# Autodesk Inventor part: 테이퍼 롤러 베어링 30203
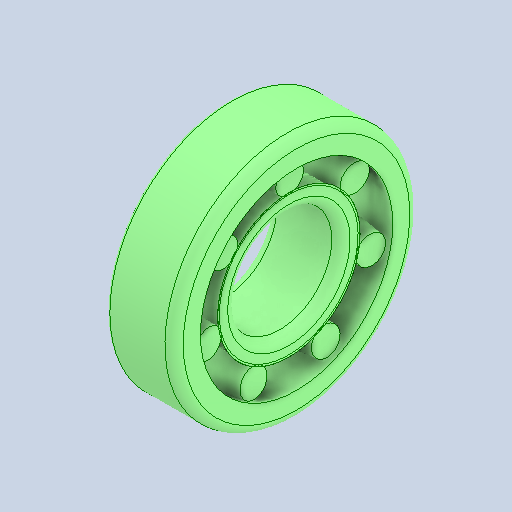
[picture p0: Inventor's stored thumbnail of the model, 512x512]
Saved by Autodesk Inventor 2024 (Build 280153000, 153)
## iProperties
Created: 2026-01
Part Number: 테이퍼 롤러 베어링 30203
Material: 강철, 연강
Description: 테이퍼 롤러 베어링
Document SubType Name: Modeling
Designer: 2-10
Density: 7.85 g/cm^3
Appearance: 기본값
Sending System: Autodesk Inventor 2026
Preprocessor: ST-DEVELOPER v20.1
Author: jhkim
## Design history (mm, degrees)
node "테이퍼 롤러 베어링 302031"
node "솔리드1"
node "솔리드2"
body "Solid1"
node "Solid1:1"
